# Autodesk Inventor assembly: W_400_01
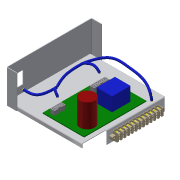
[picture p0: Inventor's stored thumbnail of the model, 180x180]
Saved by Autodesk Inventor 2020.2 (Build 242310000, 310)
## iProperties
Created: 2014-10
Part Number: W_400_01
Document SubType Name: Assembly
Designer: F.Stasiak
Catalog Web Link: www.expertbooks.pl
Manager: www.cadconsulting.pl
Company: Fabian Stasiak CAD Consulting
Author: F.Stasiak
Subject: Zbiór ćwiczeń. Autodesk Inventor 2020. Kurs Professional
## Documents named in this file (6)
- C:\2020_Kurs_Professional\R2 Wiązki\W_400_01.iam
- C:\2020_Kurs_Professional\R2 Wiązki\Komponenty\Podstawa_300_01.ipt
- C:\2020_Kurs_Professional\R2 Wiązki\Komponenty\Front_400_01.ipt
- C:\2020_Kurs_Professional\R2 Wiązki\Komponenty\LISTWA_100_01.ipt
- C:\2020_Kurs_Professional\R2 Wiązki\Komponenty\PCB_400_01.ipt
- C:\2020_Kurs_Professional\R2 Wiązki\W_400_01\AIP\przewody i wiązki przewodów\W_400_01.Wiązka przewodów1.iam
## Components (5 placed, 5 different names)
1. Podstawa_300_01:1 — Równoległy:1, Równoległy:2, Zestawiający:1, Zestawiający:2, Równoległy:3, Równoległy:4, Równoległy:5, Równoległy:6, Równoległy:7
2. Front_400_01:1 — Równoległy:1, Równoległy:2, Zestawiający:1
3. LISTWA_100_01:1 — Zestawiający:2, Równoległy:3, Równoległy:4
4. PCB_400_01:1 — Równoległy:5, Równoległy:6, Równoległy:7
5. Wiązka przewodów1 [sub-assembly]
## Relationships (9: Flush 7, Mate 2)
- Równoległy:1 [Flush]: Podstawa_300_01:1 ↔ Front_400_01:1
- Równoległy:2 [Flush]: Podstawa_300_01:1 ↔ Front_400_01:1
- Zestawiający:1 [Mate]: Podstawa_300_01:1 ↔ Front_400_01:1
- Zestawiający:2 [Mate]: Podstawa_300_01:1 ↔ LISTWA_100_01:1
- Równoległy:3 [Flush]: Podstawa_300_01:1 ↔ LISTWA_100_01:1
- Równoległy:4 [Flush]: Podstawa_300_01:1 ↔ LISTWA_100_01:1
- Równoległy:5 [Flush]: Podstawa_300_01:1 ↔ PCB_400_01:1
- Równoległy:6 [Flush]: Podstawa_300_01:1 ↔ PCB_400_01:1
- Równoległy:7 [Flush]: Podstawa_300_01:1 ↔ PCB_400_01:1
